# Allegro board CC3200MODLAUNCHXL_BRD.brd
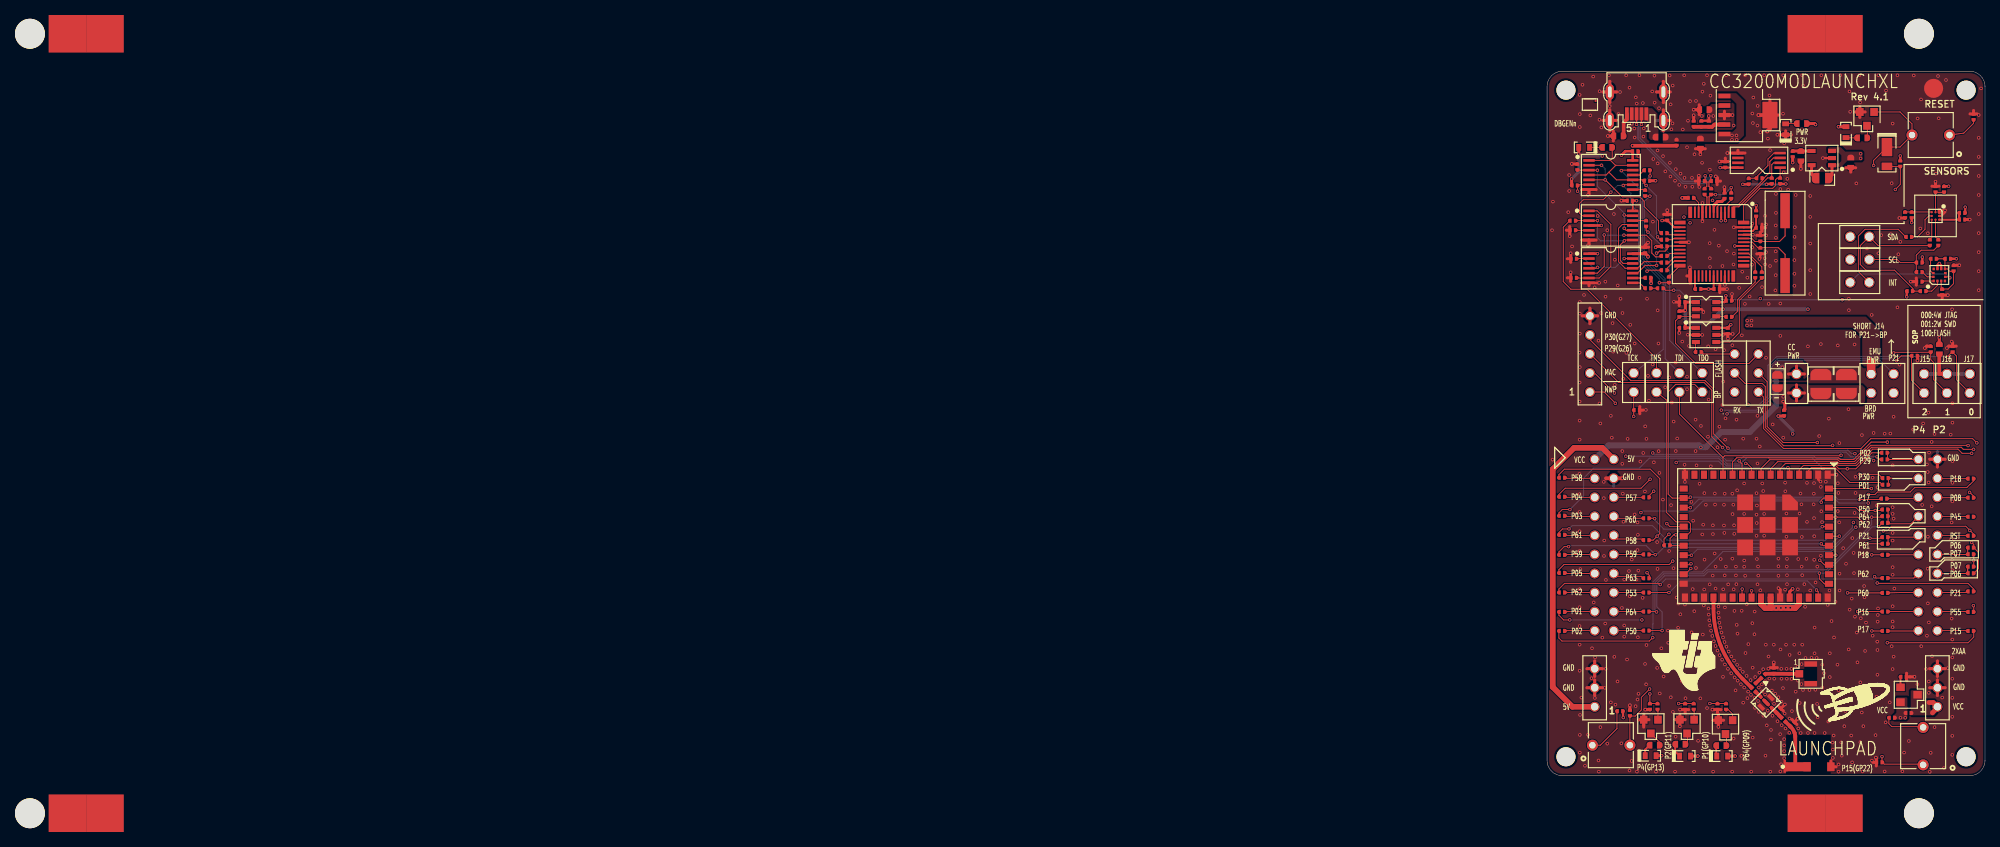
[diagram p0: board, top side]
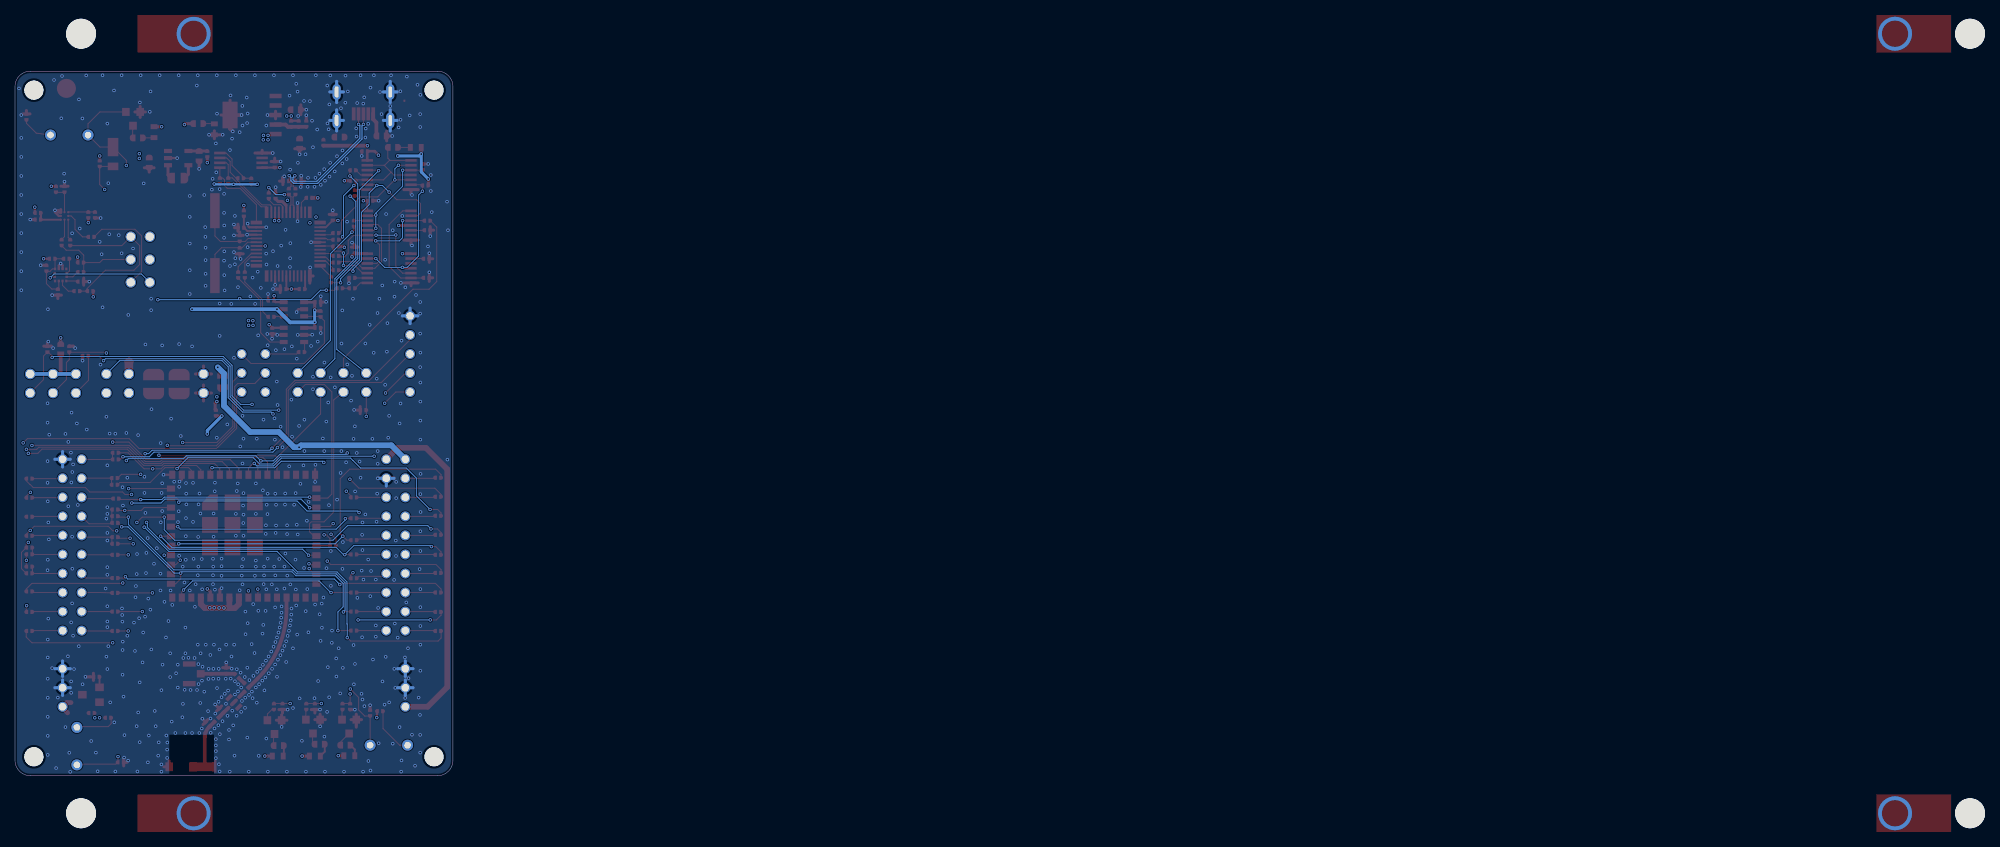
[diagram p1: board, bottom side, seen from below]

Outline 58.42 x 93.98 mm; copper layers: TOP, MID1(L2), MID2(L3), BOTTOM. Coordinates in mm from the lower left corner of the outline.
Outline path: 0,91.95 0,2.03 arc(0.6,0.6) 2.03,0 56.39,0 arc(57.82,0.6) 58.42,2.03 58.42,91.95 arc(57.82,93.38) 56.39,93.98 2.03,93.98 arc(0.6,93.38) 0,91.95

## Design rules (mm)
net group USB_D+: nets USB_D+ USB_DP
net group USB_D-: nets USB_D- USB_DM
net group RF_50OHM_6: nets N17123437 N17123480 N17123972 N17134004 N17134874 N17156940 RF_BG
nets with their own width: min track width 0.127; nets GND

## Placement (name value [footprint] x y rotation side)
C31  15pF  [C-0402S0]  21.59 86.97 180 top
C32  10uF  [C-0603S0]  20.98 88.85 90 top
C33  10uF  [C-0603S0]  20.45 84.33 180 top
C50  0.1uF  [C-0402S0]  54.23 67.69 0 top
C51  0.1uF  [C-0402S0]  55.37 74.19 270 top
C52  0.1uF  [C-0402S0]  52.7 64.52 180 top
C54  33000 pF  [C-0402S0]  23.67 77.37 0 top
C55  0.1uF  [C-0402S0]  28.27 73.1 270 top
C56  0.1uF  [C-0402S0]  16.03 74.47 0 top
C57  0.1uF  [C-0402S0]  22.63 64.92 270 top
C58  0.1uF  [C-0402S0]  23.77 81.53 0 top
C59  30pF  [C-0402S0]  28.45 71.68 0 top
C60  30pF  [C-0402S0]  28.45 70.03 180 top
C63  10uF  [C-0603S0]  33.86 82.65 180 top
C64  1.0pF  [C-0402S0]  32.71 6.87 135 top
C65  100uF  [C-1210]  39.93 52.24 0 top
C66  10uF  [C-0603S0]  40.51 81.79 180 top
C68  0.1uF  [R-0402S0]  18.03 63.18 90 top
C69  0.1uF  [C-0402S0]  24.26 63.37 270 top
C70  0.1uF  [C-0402S0]  18.03 59.75 90 top
C71  100uF  [C-1210]  36.53 52.24 0 top
C72  0.1uF  [C-0402S0]  24.1 59.33 180 top
C73  10pF  [C-0402S0]  28.83 13.28 315 top
C75  0.1uF  [C-0402S0]  11.76 83.31 270 top
C76  0.1uF  [C-0402S0]  13.08 70.1 0 top
C77  0.1uF  [C-0402S0]  11.05 76.71 90 top
D1  LED-Y  [LD-0603A]  39.88 85.85 0 top
D2  LED-G  [LD-0603A]  4.95 83.82 90 top
D4  LED-R  [LD-0603A]  31.83 86.23 0 top
D5  LED-G  [LD-0603A]  13.82 2.66 270 top
D6  LED-Y  [LD-0603A]  18.41 2.61 270 top
D7  LED-R  [LD-0603A]  23.37 2.61 270 top
D9  DIODE  [D-DFLT51AS0]  45.34 82.91 180 top
D13  V5.5MLA  [R-0402S0]  20.62 79.32 90 top
D14  V5.5MLA  [R-0402S0]  22.28 79.32 270 top
E1  AH316M245001-T  [ANT-T77H533_00C]  36.27 1.18 180 top
FB11  60R  [L-0603S0]  15.14 85.19 270 top
FB12  60R  [L-0603S0]  9.53 85.34 90 top
H1  TOOLING HOLE-1PIN-NPTH  [MTH100]  2.52 2.52 0 top
H2  TOOLING HOLE-1PIN-NPTH  [MTH100]  55.9 2.52 0 top
H3  TOOLING HOLE-1PIN-NPTH  [MTH100]  55.9 91.46 0 top
H4  TOOLING HOLE-1PIN-NPTH  [MTH100]  2.52 91.46 0 top
J1  Micro-USB  [CJ-USBSUA-160M3B-L2AT]  11.94 90.17 180 top
J2  jumper  [CN-D2X1-2_54S0]  41.71 71.91 180 top
J3  jumper  [CN-D2X1-2_54S0]  41.71 68.86 180 top
J4  jumper  [CN-D2X1-2_54S0]  41.71 65.81 180 top
J5  DNP  [CN-5X1-2_54]  5.71 56.26 90 top
J6  HEADER_3  [CN-3X1-2_54]  25.02 53.72 90 top
J7  HEADER_3  [CN-3X1-2_54]  28.19 53.72 90 top
J8  jumper  [CN-D2X1-2_54S0]  11.56 52.45 270 top
J9  jumper  [CN-D2X1-2_54S0]  14.61 52.45 270 top
J10  jumper  [CN-D2X1-2_54S0]  17.65 52.45 270 top
J11  jumper  [CN-D2X1-2_54S0]  20.7 52.45 270 top
J12  Jumper  [CN-D2X1-2_54S0]  33.27 52.32 90 top
J13  jumper  [CN-D2X1-2_54S0]  43.23 52.32 90 top
J14  jumper  [CN-D2X1-2_54S0]  46.23 52.32 90 top
J15  jumper  [CN-D2X1-2_54S0]  50.3 52.32 90 top
J16  jumper  [CN-D2X1-2_54S0]  53.35 52.32 90 top
J17  jumper  [CN-D2X1-2_54S0]  56.39 52.32 90 top
J18  CONN_U.FL  [CJ-RF-S3_1X3-3]  35.17 13.59 270 top
J19  HEADER_3  [CN-3X1-2_54]  6.35 11.73 90 top
J20  HEADER_3  [CN-3X1-2_54]  52.07 11.73 90 top
J22  CONN_RCPT_10x2  [CN-10X2-2_54C]  7.62 30.78 270 top
J23  CONN_RCPT_10x2  [CN-10X2-2_54C]  50.8 30.78 270 top
J24  MM8030-2610RJ3  [CN-MM8030S0]  29.21 9.78 225 top
L4  3.6nH  [L-0402S0]  31.53 7.47 225 top
L5  DNP  [L-0402S0]  30.9 8.68 315 top
L6  DNP  [L-0402S0]  30.24 14 0 top
L11  10uH  [L-0805]  36.7 79.73 90 top
NOREF  -  []  49.61 -10.02 90 top
NOREF#2  -  []  54.61 95.98 90 top
NOREF#3  -  []  3.81 90.98 0 top
NOREF#4  -  []  -238.79 103.99 270 top
NOREF#5  -  []  54.61 -2.02 90 top
NOREF#6  -  [unnamed#2]  5.71 89.53 180 top
NOREF#7  -  []  -254.76 115.32 0 top
NOREF#8  -  []  3.81 90.98 180 top
NOREF#9  -  []  6.81 -0.02 90 top
NOREF#10  -  []  -207.39 95.98 0 top
OP1  MD-FIDUCIAL-MARK  [TOP10L-4S0]  -207.39 -0.01 90 top
OP2  MD-FIDUCIAL-MARK  [TOP10R-4S0]  -207.39 93.98 90 top
OP3  MD-FIDUCIAL-MARK  [TOP15L-4S0]  54.61 -0.02 90 top
OP4  MD-FIDUCIAL-MARK  [TOP15R-4S0]  54.61 93.98 90 top
Q7  BSS138LT3G  [SOT-23B]  13.84 6.55 90 top
Q8  BSS138LT3G  [SOT-23B]  18.67 6.55 90 top
Q9  BSS138LT3G  [SOT-23B]  23.8 6.47 90 top
Q10  BSS138LT3G  [SOT-23B]  42.67 87.63 90 top
Q11  AP2323GN  [SOT-23D]  48.29 10.79 180 top
R4  100k  [R-0402S0]  54.1 56.9 0 top
R7  100k  [R-0402S0]  51.18 56.9 0 top
R8  2.7k  [R-0402S0]  49.02 56.01 270 top
R9  270  [R-0603S0]  52.32 56.9 180 top
R10  0 R  [R-0402S0]  1.98 39.75 270 top
R12  0R  [R-0402S0]  16 30.73 90 top
R13  100k  [R-0402S0]  11.96 48.77 270 top
R22  0 R  [R-0402S0]  1.98 29.46 270 top
R28  28  [R-0402S0]  21.89 77.93 180 top
R30  10k  [R-0402S0]  19.18 77.09 270 top
R31  0 R  [R-0402S0]  1.98 24.43 270 top
R32  10k  [R-0402S0]  31.09 79.35 0 top
R34  10k  [R-0402S0]  20.14 64.92 90 top
R35  2.2K  [R-0402S0]  28.32 79.71 270 top
R36  0 R  [R-0402S0]  56.52 24.58 270 top
R55  30.1K  [R-0402S0]  19.56 86.97 180 top
R56  52.3K  [R-0402S0]  20.57 86.97 0 top
R63  DNP  [R-0805]  30.73 52.58 180 top
R64  270  [R-0603S0]  33.99 87 90 top
R69  270  [R-0603S0]  14.35 4.06 270 top
R70  270  [R-0603S0]  17.78 4.19 270 top
R72  DNP  [R-0402S0]  47.75 74.8 0 top
R74  DNP  [R-0402S0]  27.56 12.06 135 top
R75  0 R  [R-0402S0]  27.54 11.46 225 top
R76  DNP  [R-0201S1]  28.71 10.28 45 top
R77  DNP  [R-0201S1]  29.71 9.28 225 top
R86  DNP  [R-0402S0]  52.96 78.23 0 top
R94  270  [R-0603S0]  23.24 4.01 270 top
R95  270  [R-0603S0]  42.04 85.09 270 top
R97  0 R  [R-0402S0]  49.66 67.18 270 top
R98  0 R  [R-0402S0]  53.47 68.96 270 top
R99  0 R  [R-0402S0]  48.64 74.8 180 top
R101  0 R  [R-0402S0]  55.37 75.08 270 top
R102  0 R  [R-0402S0]  49.66 65.91 270 top
R103  0 R  [R-0402S0]  51.56 68.96 90 top
R104  0 R  [R-0402S0]  50.16 64.64 270 top
R106  0 R  [R-0402S0]  51.82 78.23 180 top
R107  0 R  [R-0402S0]  52.2 71.12 0 top
R108  0 R  [R-0402S0]  51.05 71.12 0 top
R109  0 R  [R-0402S0]  17.27 84.45 180 top
R110  0 R  [R-0402S0]  32.77 82.93 0 top
R111  DNP  [R-0402S0]  48.26 71.88 90 top
R112  DNP  [R-0402S0]  31.62 48.39 0 top
R113  0 R  [R-0402S0]  15.11 65.02 90 top
R120  DNP  [R-0402S0]  48.21 8.36 90 top
R168  1k  [R-0402S0]  9.73 8.61 90 top
R169  1k  [R-0402S0]  46 7.72 90 top
R172  3.3K  [R-0402S0]  49.66 68.45 270 top
R173  3.3K  [R-0402S0]  48.39 64.64 90 top
R207  10k  [R-0402S0]  44.32 1.78 90 top
R208  10k  [R-0402S0]  11.05 8.36 0 top
R209  10k  [R-0402S0]  14.73 9.22 180 top
R210  10k  [R-0402S0]  19.56 9.22 180 top
R211  10k  [R-0402S0]  23.88 9.22 180 top
R212  100k  [R-0402S0]  22.73 9.22 0 top
R213  100k  [R-0402S0]  18.41 9.22 0 top
R214  100k  [R-0402S0]  13.72 9.22 0 top
R225  100R  [R-0402S0]  56.9 87.88 180 top
R226  100k  [R-0402S0]  47.12 81.66 180 top
R231  0 R  [R-0402S0]  1.98 32.13 270 top
R237  0 R  [R-0402S0]  1.98 27.05 270 top
R277  0 R  [R-0402S0]  47.55 13.18 90 top
R278  0 R  [R-0402S0]  13.24 26.34 270 top
R279  0 R  [R-0402S0]  13.24 24.43 270 top
R280  0 R  [R-0402S0]  56.52 37.08 270 top
R284  0 R  [R-0402S0]  56.52 21.84 270 top
R285  0 R  [R-0402S0]  45.01 42.19 270 top
R286  0 R  [R-0402S0]  45.14 39.7 270 top
R287  0 R  [R-0402S0]  1.98 37.21 270 top
R288  0 R  [R-0402S0]  1.98 34.67 270 top
R289  0 R  [R-0402S0]  1.98 21.84 270 top
R290  0 R  [R-0402S0]  1.98 19.3 270 top
R291  0 R  [R-0402S0]  13.24 21.89 270 top
R292  0 R  [R-0402S0]  56.52 32 270 top
R293  0 R  [R-0402S0]  56.52 29.54 270 top
R294  0 R  [R-0402S0]  56.52 27 270 top
R295  0 R  [R-0402S0]  56.52 39.62 270 top
R296  DNP  [R-0402S0]  56.52 30.43 270 top
R297  DNP  [R-0402S0]  56.52 27.89 270 top
R298  DNP  [R-0402S0]  45.01 43.08 270 top
R299  DNP  [R-0402S0]  45.14 38.81 270 top
R300  DNP  [R-0402S0]  45.09 26.36 270 top
R301  DNP  [R-0402S0]  45.09 24.38 270 top
R302  10k  [R-0402S0]  26.9 79.3 0 top
R303  33  [R-0402S0]  16.26 66.17 180 top
R304  33  [R-0402S0]  15.62 67.44 90 top
R305  33  [R-0402S0]  15.62 68.45 90 top
R306  33  [R-0402S0]  15.62 69.34 90 top
R307  DNP  [R-0402S0]  45.09 30.93 270 top
R308  DNP  [R-0402S0]  45.09 29.46 270 top
R309  0 R  [R-0402S0]  13.24 37.13 270 top
R310  0 R  [R-0402S0]  45.09 21.89 270 top
R311  0 R  [R-0402S0]  45.09 19.3 270 top
R312  0 R  [R-0402S0]  13.24 34.34 270 top
R313  0 R  [R-0402S0]  56.52 19.3 270 top
R314  10k  [R-0402S0]  15.62 70.61 270 top
R315  10k  [R-0402S0]  13.34 79.38 90 top
R316  33  [R-0402S0]  15.62 72.39 90 top
R317  33  [R-0402S0]  15.62 71.5 90 top
R318  10k  [R-0402S0]  3.68 78.74 270 top
R319  10k  [R-0402S0]  4.04 81.2 0 top
R320  33  [R-0402S0]  13.34 80.77 270 top
R321  33  [R-0402S0]  13.08 77.72 180 top
R322  10k  [R-0402S0]  3.56 66.42 90 top
R323  33  [R-0402S0]  3.43 74.04 90 top
R324  33  [R-0402S0]  13.21 73.66 180 top
R325  10k  [R-0402S0]  13.46 66.42 270 top
R326  270  [R-0603S0]  8 83.82 270 top
R327  33  [R-0402S0]  13.46 65.02 270 top
R328  10k  [R-0402S0]  3.56 68.96 90 top
R329  10k  [R-0402S0]  3.43 72.77 90 top
R330  33  [R-0402S0]  24.26 61.21 270 top
R331  33  [R-0402S0]  20.19 56.52 90 top
R332  33  [R-0402S0]  28.65 66.8 180 top
R333  33  [R-0402S0]  27.76 66.8 180 top
R334  DNP  [R-0402S0]  45.09 34.62 270 top
R335  0 R  [R-0402S0]  13.24 19.35 270 top
R336  DNP  [R-0402S0]  44.96 36.96 270 top
R337  DNP  [R-0402S0]  45.09 31.82 270 top
R338  470  [R-0402S0]  27.89 75.01 0 top
R339  DNP  [R-0402S0]  45.09 35.51 270 top
R340  DNP  [R-0402S0]  13.24 29.51 270 top
R341  0 R  [R-0402S0]  56.52 34.54 270 top
R342  10k  [R-0402S0]  29.97 79.35 0 top
R343  28  [R-0402S0]  21.01 77.93 180 top
R344  DNP  [R-0402S0]  45.09 33.73 270 top
R345  1.5k  [R-0402S0]  24.56 77.37 180 top
R346  DNP  [R-0402S0]  13.24 31.42 270 top
R347  100k  [R-0402S0]  17.65 61.59 0 top
SW1  1BT002-0120L  [SW-D6_2X6_2-2]  51.18 85.47 180 top
SW2  1BT002-0120L  [SW-D6_2X6_2-2]  50.16 3.94 90 top
SW3  1BT002-0120L  [SW-D6_2X6_2-2]  8.55 4.06 180 top
TP1  TP_1206  [ICT100]  51.56 91.69 180 top
U1  TI CC3101 module  [E-PMODULE-S20_5X17_5-54S]  27.91 31.95 180 top
U2  93LC46B-I/MS  [MSOP-8A]  28.27 82.09 0 top
U3  TPS73701  [SOT-223-6]  26.7 88.14 180 top
U4  SN74LVC125APWR  [SSOP-14S0]  8.51 80.14 180 top
U5  FT2232D  [TQFP-48S0]  21.97 70.92 180 top
U6  TMP006  [TBGA-3X3-8C]  51.82 74.68 180 top
U7  SN74LVC126APWR  [SSOP-14S0]  8.51 73.41 180 top
U8  TPS61097-33DBVR  [SOT-23-5]  36.65 82.39 0 top
U9  SN74LVC125APWR  [SSOP-14S0]  8.51 67.69 180 top
U10  BMA222  [TLP-2X2-12]  52.32 66.8 0 top
U11  SN74LVC1T45D  [SOT-23-6]  21.21 58.8 180 top
U12  SN74LVC1T45D  [SOT-23-6]  21.21 62.23 180 top
Y1  6MHz  [O-SMD49S12X4_8S0]  31.75 71.04 180 top

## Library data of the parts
C31 C50-C52 C54-C60 C64 C69 C70 C72 C73 C75-C77 = C-0402S0
C32 C33 C63 C66 = C-0603S0
C65 C71 = C-1210
C68 D13 D14 R4 R7 R8 R10 R12 R13 R22 R30-R32 R34-R36 R55 R56 R72 R74 R75 R86 R97-R99 R101-R104 R106-R113 R120 R168 R169 R172 R173 R207-R214 R225 R226 R231 R237 R277-R280 R284-R325 R327-R342 R344-R347 = R-0402S0
D1 D2 D4-D7 = LD-0603A
D9 = D-DFLT51AS0
E1 = ANT-T77H533_00C
FB11 FB12 = L-0603S0
H1-H4 = MTH100
J1 = CJ-USBSUA-160M3B-L2AT
J2-J4 J8-J17 = CN-D2X1-2_54S0
J5 = CN-5X1-2_54
J6 J7 J19 J20 = CN-3X1-2_54
J18 = CJ-RF-S3_1X3-3
J22 J23 = CN-10X2-2_54C
J24 = CN-MM8030S0
L4-L6 = L-0402S0
L11 = L-0805
OP1 = TOP10L-4S0
OP2 = TOP10R-4S0
OP3 = TOP15L-4S0
OP4 = TOP15R-4S0
Q7-Q10 = SOT-23B
Q11 = SOT-23D
R9 R64 R69 R70 R94 R95 R326 = R-0603S0
R28 R343 = R-0402S0: signal model: R-0402S0_28
R63 = R-0805
R76 R77 = R-0201S1
SW1-SW3 = SW-D6_2X6_2-2
TP1 = ICT100
U1 = E-PMODULE-S20_5X17_5-54S
U2 = MSOP-8A
U3 = SOT-223-6
U4 U7 U9 = SSOP-14S0
U5 = TQFP-48S0
U6 = TBGA-3X3-8C
U8 = SOT-23-5
U10 = TLP-2X2-12
U11 U12 = SOT-23-6
Y1 = O-SMD49S12X4_8S0

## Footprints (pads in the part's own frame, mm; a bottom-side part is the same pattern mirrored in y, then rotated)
ANT-T77H533_00C
  rect 0.406x0.406 smd: 1(3.163,-4.005)
  rect 0.991x1.194 smd: 2(1.595,0) 3(-1.595,0)
C-0402S0
  custom 0.127x0.127 smd: 1(0,-0.406) 2(0,0.406)
C-0603S0
  custom 0.191x0.191 smd: 1(0,-0.686) 2(0,0.686)
C-1210
  custom 0.381x0.381 smd: 1(0,-1.27) 2(0,1.27)
CJ-RF-S3_1X3-3
  rect 0.991x1.041 smd: 1(0,-1.524)
  rect 0.711x1.702 smd: 2(1.311,0) 3(-1.311,0)
CJ-USBSUA-160M3B-L2AT
  rect 0.508x1.753 smd: 1(-1.3,1.877) 2(-0.65,1.877) 3(0,1.877) 4(0.65,1.877) 5(1.3,1.877)
  oval 1.092x2.083 hole 0.483x1.473: S1(3.575,-1.05) S2(-3.575,-1.05) S3(3.575,2.75) S4(-3.575,2.75)
CN-3X1-2_54
  round 1.321 hole 0.991: 1(-2.54,0) 2(0,0) 3(2.54,0)
CN-5X1-2_54
  round 1.321 hole 0.991: 1(-5.08,0) 2(-2.54,0) 3(0,0) 4(2.54,0) 5(5.08,0)
CN-10X2-2_54C
  round 1.321 hole 0.991: 1(-11.43,-1.27) 2(-11.43,1.27) 3(-8.89,-1.27) 4(-8.89,1.27) 5(-6.35,-1.27) 6(-6.35,1.27) 7(-3.81,-1.27) 8(-3.81,1.27) 9(-1.27,-1.27) 10(-1.27,1.27) 11(1.27,-1.27) 12(1.27,1.27) 13(3.81,-1.27) 14(3.81,1.27) 15(6.35,-1.27) 16(6.35,1.27) 17(8.89,-1.27) 18(8.89,1.27) 19(11.43,-1.27) 20(11.43,1.27)
CN-D2X1-2_54S0
  round 1.397 hole 1.092: 1(-1.27,0) 2(1.27,0)
CN-MM8030S0
  rect 0.356x0.356 smd: 1(0,-0.978) 4(0,0.978)
  rect 0.508x1.016 smd: 2(-0.904,0) 3(0.904,0)
D-DFLT51AS0
  rect 1.422x1.016 smd: 1(0,1.626)
  rect 1.422x2.438 smd: 2(0,-0.95)
E-PMODULE-S20_5X17_5-54S
  rect 0.813x1.092 smd: 1(-9.525,-8.196) 2(-8.255,-8.196) 3(-6.985,-8.196) 4(-5.715,-8.196) 5(-4.445,-8.196) 6(-3.175,-8.196) 7(-1.905,-8.196) 8(-0.635,-8.196) 9(0.635,-8.196) 10(1.905,-8.196) 11(3.175,-8.196) 12(4.445,-8.196) 13(5.715,-8.196) 14(6.985,-8.196) 15(8.255,-8.196) 16(9.525,-8.196) 28(9.525,8.196) 29(8.255,8.196) 30(6.985,8.196) 31(5.715,8.196) 32(4.445,8.196) 33(3.175,8.196) 34(1.905,8.196) 35(0.635,8.196) 36(-0.635,8.196) 37(-1.905,8.196) 38(-3.175,8.196) 39(-4.445,8.196) 40(-5.715,8.196) 41(-6.985,8.196) 42(-8.255,8.196) 43(-9.525,8.196)
  rect 1.092x0.813 smd: 17(9.696,-6.35) 18(9.696,-5.08) 19(9.696,-3.81) 20(9.696,-2.54) 21(9.696,-1.27) 22(9.696,0) 23(9.696,1.27) 24(9.696,2.54) 25(9.696,3.81) 26(9.696,5.08) 27(9.696,6.35) 44(-9.696,6.35) 45(-9.696,5.08) 46(-9.696,3.81) 47(-9.696,2.54) 48(-9.696,1.27) 49(-9.696,0) 50(-9.696,-1.27) 51(-9.696,-2.54) 52(-9.696,-3.81) 53(-9.696,-5.08) 54(-9.696,-6.35)
  custom 0.527x0.527 smd: 55(-4.5,-4.5)
  rect 2.108x2.108 smd: 56(-1.5,-4.5) 57(1.5,-4.5) 58(-4.5,-1.5) 59(-1.5,-1.5) 60(1.5,-1.5) 61(-4.5,1.5) 62(-1.5,1.5) 63(1.5,1.5)
ICT100
  round 2.54 smd: 1(0,0)
L-0402S0
  custom 0.127x0.127 smd: 1(0,-0.406) 2(0,0.406)
L-0603S0
  custom 0.191x0.191 smd: 1(0,-0.686) 2(0,0.686)
L-0805
  custom 0.254x0.254 smd: 1(0,-0.889) 2(0,0.889)
LD-0603A
  rect 0.914x0.66 smd: 1(0,0.728) 2(0,-0.728)
MSOP-8A
  rect 1.524x0.356 smd: 1(2.819,-0.975) 2(2.819,-0.325) 3(2.819,0.325) 4(2.819,0.975) 5(-2.819,0.975) 6(-2.819,0.325) 7(-2.819,-0.325) 8(-2.819,-0.975)
MTH100
  round 2.54 hole 2.54 unplated: (0,0)
O-SMD49S12X4_8S0
  rect 1.27x4.674 smd: 1(0,-4.331) 2(0,4.331)
R-0201S1
  custom 0.076x0.076 smd: 1(0,-0.229) 2(0,0.229)
R-0402S0
  custom 0.127x0.127 smd: 1(0,-0.406) 2(0,0.406)
R-0603S0
  custom 0.191x0.191 smd: 1(0,-0.686) 2(0,0.686)
R-0805
  custom 0.254x0.254 smd: 1(0,-0.889) 2(0,0.889)
SOT-23-5
  rect 1.067x0.559 smd: 1(1.359,-0.95) 2(1.359,0) 3(1.359,0.95) 4(-1.359,0.95) 5(-1.359,-0.95)
SOT-23-6
  rect 1.067x0.559 smd: 1(1.359,-0.95) 2(1.359,0) 3(1.359,0.95) 4(-1.359,0.95) 5(-1.359,0) 6(-1.359,-0.95)
SOT-23B
  rect 1.067x1.016 smd: 1(0.92,-0.951) 2(0.92,0.951) 3(-0.921,0)
SOT-23D
  rect 1.143x1.016 smd: 1(1.143,-0.991) 2(1.143,0.991) 3(-1.143,0)
SOT-223-6
  rect 1.6x0.61 smd: 1(3.035,-2.54) 2(3.035,-1.27) 3(3.035,0) 4(3.035,1.27) 5(3.035,2.54)
  rect 2.007x3.556 smd: 6(-3.035,0)
SSOP-14S0
  rect 1.524x0.356 smd: 1(2.918,-1.95) 2(2.918,-1.3) 3(2.918,-0.65) 4(2.918,0) 5(2.918,0.65) 6(2.918,1.3) 7(2.918,1.95) 8(-2.918,1.95) 9(-2.918,1.3) 10(-2.918,0.65) 11(-2.918,0) 12(-2.918,-0.65) 13(-2.918,-1.3) 14(-2.918,-1.95)
SW-D6_2X6_2-2
  round 1.473 hole 0.864: T1(-2.5,0) T2(2.5,0)
TBGA-3X3-8C
  round 0.305 smd: A1(-0.5,-0.5) A2(-0.5,0) A3(-0.5,0.5) B1(0,-0.5) B3(0,0.5) C1(0.5,-0.5) C2(0.5,0) C3(0.5,0.5)
TLP-2X2-12
  rect 0.305x0.356 smd: 1(-0.75,-0.803) 2(-0.25,-0.803) 3(0.25,-0.803) 4(0.75,-0.803) 7(0.75,0.803) 8(0.25,0.803) 9(-0.25,0.803) 10(-0.75,0.803)
  rect 0.356x0.305 smd: 5(0.803,-0.25) 6(0.803,0.25) 11(-0.803,0.25) 12(-0.803,-0.25)
TOP10L-4S0
  round 3.988 hole 3.988 unplated: (-5.004,-5.004)
  rect 5.004x5.004 smd: (-5.004,-10.008) (-5.004,-15.011)
  round 1.016 smd: (-5.004,-15.011) 1(-5.004,-10.008)
TOP10R-4S0
  round 3.988 hole 3.988 unplated: (5.004,-5.004)
  rect 5.004x5.004 smd: (5.004,-10.008) (5.004,-15.011)
  round 1.016 smd: (5.004,-15.011) 1(5.004,-10.008)
TOP15L-4S0
  round 1.016 smd: (-5.001,20.018) 1(-5.001,15.014)
  rect 5.004x5.004 smd: (-5.001,20.018) (-5.001,15.014)
  round 3.988 hole 3.988 unplated: (-5.001,5.006)
TOP15R-4S0
  round 1.016 smd: (5.006,20.018) 1(5.006,15.014)
  rect 5.004x5.004 smd: (5.006,20.018) (5.006,15.014)
  round 3.988 hole 3.988 unplated: (5.006,5.006)
TQFP-48S0
  rect 0.508x1.524 smd: 1(-2.878,-4.249) 12(2.878,-4.249) 25(2.878,4.249) 36(-2.878,4.249)
  rect 0.254x1.524 smd: 2(-2.251,-4.249) 3(-1.751,-4.249) 4(-1.25,-4.249) 5(-0.75,-4.249) 6(-0.25,-4.249) 7(0.25,-4.249) 8(0.75,-4.249) 9(1.25,-4.249) 10(1.75,-4.249) 11(2.25,-4.249) 26(2.25,4.249) 27(1.75,4.249) 28(1.25,4.249) 29(0.75,4.249) 30(0.25,4.249) 31(-0.25,4.249) 32(-0.75,4.249) 33(-1.25,4.249) 34(-1.751,4.249) 35(-2.251,4.249)
  rect 1.524x0.508 smd: 13(4.249,-2.878) 24(4.249,2.878) 37(-4.249,2.878) 48(-4.249,-2.878)
  rect 1.524x0.254 smd: 14(4.249,-2.251) 15(4.249,-1.751) 16(4.249,-1.25) 17(4.249,-0.75) 18(4.249,-0.25) 19(4.249,0.25) 20(4.249,0.75) 21(4.249,1.25) 22(4.249,1.75) 23(4.249,2.25) 38(-4.249,2.25) 39(-4.249,1.75) 40(-4.249,1.25) 41(-4.249,0.75) 42(-4.249,0.25) 43(-4.249,-0.25) 44(-4.249,-0.75) 45(-4.249,-1.25) 46(-4.249,-1.751) 47(-4.249,-2.251)
unnamed#2
  rect 0.254x0.305 smd: 1(-0.762,-0.508)

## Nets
GND: C32.2 C33.2 C50.2 C51.2 C52.2 C54.2 C55.2 C56.2 C57.2 C58.2 C59.2 C60.2 C63.2 C64.1 C65.2 C66.2 C68.2 C69.2 C70.2 C71.2 C72.2 C75.2 C76.2 C77.2 D4.2 D13.2 D14.2 E1.2 E1.3 FB12.2 J1.S1 J1.S2 J1.S3 J1.S4 J5.5 J18.2 J18.3 J19.2 J19.3 J20.2 J20.3 J22.4 J23.2 J24.2 J24.3 L5.2 L6.2 Q7.2 Q8.2 Q9.2 Q10.2 R4.2 R7.2 R8.2 R13.2 R55.1 R72.1 R102.1 R106.1 R207.2 R208.2 R212.1 R213.1 R214.1 R225.1 R277.1 R319.2 R322.2 R325.2 R328.2 R329.2 TP1.1 U1.1 U1.2 U1.16 U1.27 U1.28 U1.30 U1.32 U1.38 U1.43 U1.55 U1.56 U1.57 U1.58 U1.59 U1.60 U1.61 U1.62 U1.63 U2.5 U3.3 U3.6 U4.7 U5.9 U5.18 U5.25 U5.34 U5.45 U5.47 U6.A1 U6.A2 U7.7 U8.2 U9.7 U10.8 U10.9 U11.2 U11.5 U12.2
VBAT_CC: C65.1 C71.1 J12.1 R63.2 R112.2 U1.36 U1.37 U1.40
VBUS_USB1: C33.1 FB11.2 R109.1 R338.2 U3.1 U3.5 U5.3 U5.4 U5.42
VCC_BRD: C66.1 C68.1 C70.1 D1.1 D5.1 D6.1 D7.1 J12.2 J13.1 J22.1 L11.1 Q11.2 R9.1 R63.1 R64.1 R86.2 R98.2 R99.2 R101.2 R120.2 R168.1 R169.1 R172.2 R173.2 R226.1 R347.2 U8.1 U8.3 U11.1 U12.1 U12.5
VCC_DCDC_3V3: C63.1 R110.2 U8.4
VCC_LDO_3V3: C31.1 C32.1 C56.1 C57.1 C58.1 C69.1 C72.1 C75.1 C76.1 C77.1 D2.1 J13.2 R30.1 R32.1 R34.1 R56.2 R302.1 R314.1 R315.1 R318.1 R342.1 U2.8 U3.2 U4.14 U5.14 U5.31 U7.4 U7.14 U9.1 U9.14 U11.6 U12.6
VCC_MCU_5V: J19.1 J22.2 R109.2
VDD_FLASH: R110.1 R112.1 U1.39
BRD_JTAG_TCK: J8.1 R320.2
BRD_JTAG_TDI: J10.1 R321.2
BRD_JTAG_TDO: J11.1 R324.2
BRD_JTAG_TMS: J9.1 R323.2
CC_GPIO_00: R335.2 R344.1 U1.44
CC_GPIO_01: J7.2 U1.46
CC_GPIO_02: J6.2 U1.47
CC_GPIO_03: R10.1 R346.2 U1.48
CC_GPIO_04: R22.1 R340.2 U1.49
CC_GPIO_05: J5.2 R301.1 R312.2 U1.50
CC_GPIO_06: R231.1 R307.1 U1.51
CC_GPIO_07: J5.1 R31.1 R300.1 R339.1 U1.52
CC_GPIO_08: R278.2 U1.53
CC_GPIO_09: R211.1 R212.2 R291.2 R334.1 U1.54
CC_GPIO_10: J3.2 R210.1 R213.2 R289.1 R299.1 U1.3
CC_GPIO_11: J2.2 R209.1 R214.2 R290.1 R298.1 U1.4
CC_GPIO_12: R288.1 U1.9
CC_GPIO_13: J4.1 R111.2 R208.1 R287.1 SW3.T1 U1.10
CC_GPIO_14: R237.1 U1.5
CC_GPIO_15: R294.2 R296.2 U1.6
CC_GPIO_16: R293.2 R297.2 U1.7
CC_GPIO_17: R280.2 U1.8
CC_GPIO_22: R207.1 R313.2 SW2.T1 U1.11
CC_GPIO_23: J10.2 R310.1 U1.12
CC_GPIO_24: J11.2 R311.1 R336.1 U1.18
CC_GPIO_26: J5.3 R285.1 U1.25
CC_GPIO_27: J5.4 R286.1 U1.26
CC_GPIO_28: R295.2 R308.1 U1.19
CC_GPIO_30: R279.2 U1.42
CC_GPIO_31: R341.2
CC_NRESET: D9.2 Q10.1 R113.1 SW1.T2 U1.35
DBG_RST_N: R314.2 U5.19 U9.10
DBGENN: R315.2 R317.2 R326.2 U4.1 U4.4 U4.10 U4.13
DBGMOD: R316.2 U4.2 U4.5
FT_CS: R306.2 U7.9 U9.5
FT_DI: R305.2 U7.11 U9.11
FT_DO: R304.2 U4.9 U7.2
FT_SK: R303.2 U4.12
FTDI_RX: R330.2 R333.2
FTDI_TX: R332.2 U11.4
JTAG_TCK: J8.2 R13.1 U1.21
JTAG_TMS: J9.2 U1.22
LP_GPIO_01: J7.1 R284.2
LP_GPIO_02: J6.1 R309.2
LP_GPIO_25: J14.1 R36.2 R337.1
LP_RESET_OUT: D9.1 R226.2 R292.2
RF_BG: R74.2 R75.1 U1.31
SENS_I2C_SCL: J3.1 R97.1 R107.1 R172.1
SENS_I2C_SDA: J2.1 R104.1 R108.1 R173.1
SOP0: J17.1 R4.1 U1.34
SOP1: J16.1 R7.1 U1.24
SOP2/TCXO_EN: J15.1 R8.1 R12.2
SRSTN: R113.2 R327.2
TEMP_INTR: R111.1 U6.C2
USB_D+: D14.1 J1.3 R28.1
USB_D-: D13.1 J1.2 R343.1
USB_DM: R343.2 U5.8
USB_DP: R28.2 R345.1 U5.7
N185612: C50.1 C52.1 R98.1 R103.1 U10.3 U10.7
N185801: C51.1 R101.1 U6.A3
N186121: R102.2 U10.1
N186159: R103.2 U10.11
N186206: R97.2 U10.12
N186210: R104.2 U10.2
N187169: R72.2 R99.1 U6.C1
N187173: R86.1 R106.2 U6.B1
N187525: R107.2 U6.B3
N187543: R108.2 U6.C3
N187626: J4.2 U10.5
N195183: D4.1 R64.2
N195451: C31.2 R55.2 R56.1 U3.4
N292143: J20.1 Q11.3 R120.1
N311613: R225.2 SW1.T1
N311877: R168.2 SW3.T2
N311889: R169.2 SW2.T2
N312530: D7.2 R94.1
N312602: D5.2 R69.1
N312606: D6.2 R70.1
N312650: Q9.3 R94.2
N312654: Q8.3 R70.2
N312670: Q7.3 R69.2
N312782: Q7.1 R209.2
N312798: Q8.1 R210.2
N312802: Q9.1 R211.2
N329065: Q11.1 R277.2
N394921: L11.2 U8.5
N487570: C54.1 U5.6
N487672: C55.1 R338.1 U5.46
N487804: R345.2 U5.5
N487824: R34.2 U5.26
N487832: R30.2 U5.10
N487932: R333.1 U5.39
N488104: R332.1 U5.40
N488180: R342.2 U2.2 U5.1
N488188: R32.2 U2.1 U5.48
N488454: R303.1 U5.24
N488458: R304.1 U5.23
N488478: R35.1 R302.2 U2.4
N488614: R35.2 U2.3 U5.2
N488778: C60.1 U5.43 Y1.2
N488782: C59.1 U5.44 Y1.1
N489641: R305.1 U5.22
N489651: R306.1 U5.21
N490588: FB11.1 J1.1
N490596: FB12.1 J1.5
N507782: R317.1 U5.17
N507786: R316.1 U5.16
N508362: R318.2 U4.6 U9.4 U9.13
N508615: R319.1 U4.3 U7.10 U7.13
N509670: R320.1 U4.11
N509674: R321.1 U4.8
N511498: R322.1 U7.1 U9.6
N512182: R323.1 U7.3 U7.8 U9.12
N512199: R324.1 U7.12
N517852: R325.1 U9.9
N517913: D2.2 R326.1
N518669: R327.1 U9.8
N519131: R329.1 U7.5
N519138: R328.1 U9.2
N16837579: J15.2 J16.2 J17.2 R9.2
N16966302: J14.2 R12.1 U1.23
N17067937: J22.18 R291.1
N17067943: J22.9 R231.2
N17067945: J22.13 R237.2
N17067955: J22.14 R278.1
N17067957: J22.16 R279.1
N17067979: J23.6 R280.1
N17067993: J23.18 R284.1
N17068333: J23.8 R341.1
N17068401: J7.3 R347.1 U12.3
N17068413: J22.10 R346.1
N17068423: J22.12 R340.1
N17068425: R330.1 U12.4
N17068635: J22.3 R10.2
N17068637: J22.19 R290.2
N17068639: J22.5 R287.2
N17068641: J22.7 R288.2
N17068645: J22.15 R31.2
N17068647: J22.17 R289.2
N17068649: J6.3 R331.1
N17068681: R331.2 U11.3
N17068737: J23.7 R334.2 R339.2 R344.2
N17068769: J23.16 R36.1
N17068771: J23.14 R294.1 R297.1
N17068783: J23.4 R295.1
N17068785: J23.10 R292.1
N17068787: J23.12 R293.1 R296.1
N17068892: J23.3 R286.2 R299.2
N17068894: J23.5 R336.2
N17068898: J23.9 R307.2 R337.2
N17068900: J23.11 R308.2
N17068902: J23.13 R300.2
N17068904: J23.15 R301.2
N17068906: J23.17 R310.2
N17068908: J23.19 R311.2
N17068924: J23.1 R285.2 R298.2
N17069150: J22.6 R309.1
N17069152: J22.8 R312.1
N17069176: J22.11 R22.2
N17069198: J23.20 R313.1
N17069292: J22.20 R335.1
N17097905: D1.2 R95.1
N17097907: Q10.3 R95.2
N17123437: C73.2 J18.1 L6.1
N17123480: C73.1 R74.1
N17123972: J24.4 L4.1 L5.1 R77.2
N17134004: C64.2 E1.1 L4.2
N17134874: J24.1 R75.2 R76.2
N17156940: R76.1 R77.1

Pads without a net: J1 4; NOREF#6 1; OP1 1; OP2 1; OP3 1; OP4 1; U1 13 14 15 17 20 29 33 41 45; U2 6 7; U5 11 12 13 15 20 27 28 29 30 32 33 35 36 37 38 41; U7 6; U9 3; U10 4 6 10

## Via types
v1: diameter 0.457, hole 0.254, TOP to BOTTOM, 1048 vias

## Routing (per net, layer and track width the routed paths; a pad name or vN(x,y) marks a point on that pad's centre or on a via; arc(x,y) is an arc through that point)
GND: length 305.8
  TOP w0.305: v1(24,64.92) 23.98,64.9 23.06,64.9 C57.2 ; v1(28.32,68.94) 28.45,69.06 C60.2 ; C70.2 v1(17.63,59.05) ; 18.39,40.89 U1.16 v1(18.39,39.19) ; v1(24.91,73.17) U5.47 27.17,73.17 27.3,73.3 ; v1(20.73,73.96) 20.72,73.97 U5.9 20.72,76.4 v1(20.73,76.4) ; v1(20.7,58.8) U11.2 18.8,58.8 v1(18.77,58.83) ; U8.2 v1(36.79,82.39) ; v1(12.17,82.68) C75.2 ; C59.2 v1(29.21,72.09) ; U12.2 20.6,62.23 20.85,61.98 v1(20.85,61.85) ; v1(36.47,39.24) 36.44,39.24 36.17,39.52 U1.2 ; U6.A2 52.58,74.68 53.09,75.18 v1(53.09,75.44) 52.58,75.44 U6.A1 ; U5.45 v1(27.46,72.17) ; v1(38.61,40.15) U1.1 ; v1(19.05,67.82) 19.05,66.71 U5.25 ; C72.2 v1(24.77,58.93) ; U11.5 v1(23.44,58.8) ; U5.34 23.72,65.74 23.72,65.74 v1(23.72,65.48) ; C69.2 v1(24.66,64.26) ; U10.8 52.57,68.08 v1(52.32,68.33) 52.07,68.08 U10.9 ; C68.2 v1(17.63,63.96)
  TOP w0.356: R322.2 v1(3.15,67.16) ; U9.7 v1(6.94,65.74)
  TOP w0.406: R212.1 v1(22.05,8.81) ; R212.1 23.2,8.81 ; R212.1 22.73,8.36 ; C57.2 23.04,65.39 ; C57.2 v1(24,64.92) ; C57.2 23.04,64.45 ; C58.2 v1(22.99,81.94) ; C58.2 24.25,81.94 ; C58.2 23.77,82.39 ; C56.2 16.5,74.88 ; C56.2 v1(16.03,75.44) ; C56.2 15.56,74.88 ; U2.5 25.45,83.44 ; U2.5 26.4,83.07 ; U2.5 v1(24.04,83.07) ; 5.32,11.73 J19.2 ; J19.2 6.35,12.76 ; J19.2 7.38,11.73 ; J19.2 6.35,10.7 ; 52.07,13.24 J20.3 ; J20.3 53.1,14.27 ; J20.3 52.07,15.3 ; J20.3 51.04,14.27 ; C63.2 v1(33.86,80.95) ; C64.1 v1(33.43,7.59) ; C64.1 33.33,6.83 ; C64.1 32.66,7.49 ; R277.1 47.96,13.65 ; R277.1 47.96,12.71 ; R277.1 v1(49.02,13.18) ; R208.2 v1(11.05,9.4) ; 28.45,72.53 C59.2 27.98,72.09 ; C33.2 21.1,83.64 ; C33.2 19.8,83.64 ; C33.2 v1(20.45,82.91) ; C54.2 23.67,78.49 v1(23.65,78.51) ; 24.1,58.48 C72.2 23.63,58.93 ; J1.S2 15.51,92.63 ; J1.S2 14.6,91.22 ; J1.S2 16.43,91.22 ; J1.S2 15.51,89.81 ; v1(5.46,77.47) 5.59,77.6 U4.7 ; C51.2 v1(56.39,74.19) ; U3.3 v1(24.74,88.14) ; U3.3 23.66,87.64 ; U3.3 23.66,88.63 ; J20.2 52.07,12.76 ; J20.2 51.04,11.73 ; J20.2 53.1,11.73 ; J20.2 52.07,10.7 ; R207.2 43.92,2.36 v1(43.87,2.41) ; R207.2 43.47,1.78 ; R207.2 43.92,1.31 ; 8.36,86.01 J1.S3 ; J1.S3 8.36,88.83 ; J1.S3 7.45,87.42 ; J1.S3 9.28,87.42 ; Q9.2 v1(22.85,6.51) ; Q9.2 22.85,8.12 ; Q9.2 22.15,7.39 ; Q9.2 23.55,7.39 ; R4.2 54.57,57.3 ; R4.2 54.1,57.75 ; R4.2 53.59,57.3 v1(53.34,57.05) ; 52.66,75.18 U6.A1 52.32,75.52 ; 2.7,66.42 R322.2 3.15,65.95 ; C32.2 20.29,89.5 ; C32.2 20.29,88.2 ; C32.2 v1(19.56,88.85) ; D14.2 22.71,79.35 22.71,79.76 v1(22.5,79.96) ; D14.2 23.13,79.32 ; D14.2 22.68,79.8 ; D14.2 22.68,78.85 ; J5.5 5.71,62.37 ; J5.5 6.74,61.34 ; J5.5 5.71,60.31 ; J5.5 4.69,61.34 ; J19.3 6.35,15.3 ; J19.3 7.38,14.27 ; J19.3 5.32,14.27 ; J19.3 6.35,13.24 ; R13.2 12.82,48.77 ; R13.2 12.37,49.24 ; R13.2 12.37,48.3 ; v1(30.86,25.02) 31.09,24.79 U1.38 ; 17.63,62.71 C68.2 17.18,63.18 ; R329.2 v1(3.02,71.98) ; R329.2 3.02,73.24 ; R329.2 2.58,72.77 ; 31.83,84.98 D4.2 ; D4.2 31.83,86.03 ; D4.2 v1(30.72,85.5) ; D4.2 v1(32.54,85.5) ; 51.34,78.64 R106.1 ; R106.1 52.29,78.64 ; R106.1 v1(51.82,79.25) ; 18.65,66.67 U5.25 ; U5.25 19.09,67.62 ; U5.25 19.09,65.71 ; Q7.2 13.59,7.47 ; Q7.2 12.89,6.48 ; Q7.2 12.19,7.47 ; Q7.2 12.89,8.2 ; 3.15,68.49 R328.2 ; R328.2 v1(3.15,69.7) ; R328.2 2.7,68.96 ; 19.77,79.32 D13.2 ; D13.2 20.24,79.35 v1(20.24,80.04) ; D13.2 20.22,78.85 ; D13.2 20.22,79.8 ; C50.2 v1(54.99,68.1) ; 29.77,14.41 L6.2 ; L6.2 v1(30.24,15.11) ; L6.2 30.71,14.41 ; R213.1 18.89,8.81 ; R213.1 18.41,8.36 ; R213.1 v1(17.73,8.81) ; FB12.2 v1(8.1,85.34) ; FB12.2 8.84,84.7 ; FB12.2 8.84,85.99 ; L5.2 31.52,8.63 ; L5.2 v1(31.72,9.5) ; L5.2 30.85,9.3 ; U4.7 6.54,78.19 ; U4.7 4.64,78.19 ; v1(50.39,57.05) 50.65,57.3 R7.2 ; Q8.2 17.72,8.2 ; Q8.2 18.42,7.47 ; Q8.2 v1(17.72,6.58) ; Q8.2 17.02,7.47 ; U7.7 5.59,70.87 v1(5.46,70.74) ; U7.7 6.54,71.46 ; U7.7 4.64,71.46 ; 15.51,86.01 J1.S4 ; J1.S4 16.43,87.42 ; J1.S4 15.51,88.83 ; Q10.2 41.72,89.27 ; Q10.2 41.02,88.55 ; Q10.2 42.42,88.55 ; Q10.2 41.72,87.83 ; 52.7,63.66 C52.2 ; C52.2 v1(53.47,64.11) ; C52.2 52.23,64.11 ; R102.1 49.25,66.38 ; R102.1 49.25,65.44 ; R102.1 v1(48.51,65.91) ; v1(3.3,81.61) 3.31,81.61 R319.2 ; R225.1 57.37,88.29 ; R225.1 56.9,88.74 ; R225.1 56.42,88.29 ; v1(49.4,55.37) 49.43,55.4 R8.2 ; 37.86,1.97 E1.3 38.55,1.18 ; 39.86,81.1 C66.2 ; C66.2 40.51,80.53 ; C66.2 41.16,81.1 ; R55.1 v1(19.56,88.11) ; J1.S1 8.36,92.63 ; J1.S1 7.45,91.22 ; J1.S1 8.36,89.81 ; J1.S1 9.28,91.22 ; C77.2 v1(9.91,76.71) ; 27.98,69.62 C60.2 28.92,69.62 ; 52.07,41.18 J23.2 ; J23.2 51.04,42.21 ; J23.2 53.1,42.21 ; 12.61,70.51 C76.2 ; C76.2 13.55,70.51 ; C76.2 13.08,70.74 v1(13.46,71.12) ; 4.64,65.74 U9.7 5.59,65.37 ; 30.93,88.14 U3.6 29.73,90.11 ; 28.68,72.63 C55.2 ; C55.2 29.12,73.1 ; C55.2 28.68,73.57 ; R325.2 v1(13.87,65.68) ; R214.1 v1(13.08,8.81) ; R72.1 v1(46.99,74.4) ; U5.18 v1(18.92,71.17)
  TOP w0.508: 7.86,39.67 J22.4 v1(10.03,39.67) ; v1(29.36,85.95) 29.73,86.32 U3.6 v1(28.19,88.14)
  MID1(L2) w0.406: J5.5 6.69,61.34 ; J5.5 4.74,61.34 ; J5.5 5.71,62.32 ; J5.5 5.71,60.36 ; J20.2 53.05,11.73 ; J20.2 51.09,11.73 ; J20.2 52.07,10.75 ; J20.2 52.07,12.71 ; 5.37,11.73 J19.2 ; J19.2 7.33,11.73 ; J19.2 6.35,10.75 ; J19.2 6.35,12.71 ; J1.S3 9.11,87.42 ; J1.S3 8.36,88.65 ; J1.S3 8.36,86.19 ; J1.S3 7.61,87.42 ; J1.S2 15.51,92.45 ; J1.S2 14.76,91.22 ; J1.S2 15.51,89.99 ; J1.S2 16.26,91.22 ; J22.4 9.87,39.67 ; J22.4 7.91,39.67 ; J22.4 8.89,40.65 ; J22.4 8.89,38.69 ; J1.S1 8.36,92.45 ; J1.S1 8.36,89.99 ; J1.S1 7.61,91.22 ; J1.S1 9.11,91.22 ; 6.35,13.29 J19.3 ; J19.3 5.37,14.27 ; J19.3 6.35,15.25 ; J19.3 7.33,14.27 ; J20.3 52.07,15.25 ; J20.3 53.05,14.27 ; J20.3 52.07,13.29 ; J20.3 51.09,14.27 ; 15.51,86.19 J1.S4 ; J1.S4 15.51,88.65 ; J1.S4 14.76,87.42 ; J1.S4 16.26,87.42 ; 52.07,41.23 J23.2 ; J23.2 52.07,43.19 ; J23.2 53.05,42.21 ; J23.2 51.09,42.21
  MID2(L3) w0.406: 15.51,89.99 J1.S2 ; J1.S2 14.76,91.22 ; J1.S2 16.26,91.22 ; J1.S2 15.51,92.45 ; 5.37,11.73 J19.2 ; J19.2 6.35,12.71 ; J19.2 6.35,10.75 ; J19.2 7.33,11.73 ; J20.3 52.07,15.25 ; J20.3 53.05,14.27 ; J20.3 52.07,13.29 ; J20.3 51.09,14.27 ; J20.2 53.05,11.73 ; J20.2 51.09,11.73 ; J20.2 52.07,10.75 ; J20.2 52.07,12.71 ; 8.89,38.69 J22.4 ; J22.4 9.87,39.67 ; J22.4 7.91,39.67 ; J22.4 8.89,40.65 ; 6.35,13.29 J19.3 ; J19.3 7.33,14.27 ; J19.3 6.35,15.25 ; J19.3 5.37,14.27 ; J1.S4 15.51,88.65 ; J1.S4 15.51,86.19 ; J1.S4 14.76,87.42 ; J1.S4 16.26,87.42 ; J1.S1 8.36,92.45 ; J1.S1 7.61,91.22 ; J1.S1 9.11,91.22 ; J1.S1 8.36,89.99 ; 5.71,60.36 J5.5 ; J5.5 4.74,61.34 ; J5.5 5.71,62.32 ; J5.5 6.69,61.34 ; 7.61,87.42 J1.S3 ; J1.S3 8.36,88.65 ; J1.S3 9.11,87.42 ; J1.S3 8.36,86.19 ; 52.07,41.23 J23.2 ; J23.2 51.09,42.21 ; J23.2 53.05,42.21 ; J23.2 52.07,43.19
  BOTTOM w0.406: J1.S3 9.28,87.42 ; J1.S3 8.36,86.01 ; J1.S3 8.36,88.83 ; J1.S3 7.45,87.42 ; J20.2 52.07,12.76 ; J20.2 53.1,11.73 ; J20.2 52.07,10.7 ; J20.2 51.04,11.73 ; 52.07,13.24 J20.3 ; J20.3 52.07,15.3 ; J20.3 53.1,14.27 ; J20.3 51.04,14.27 ; 15.51,86.01 J1.S4 ; J1.S4 16.43,87.42 ; J1.S4 14.6,87.42 ; J1.S4 15.51,88.83 ; J19.3 6.35,15.3 ; J19.3 6.35,13.24 ; J19.3 7.38,14.27 ; J19.3 5.32,14.27 ; J5.5 6.74,61.34 ; J5.5 5.71,62.37 ; J5.5 4.69,61.34 ; J5.5 5.71,60.31 ; J23.2 52.07,43.24 ; J23.2 52.07,41.18 ; J23.2 53.1,42.21 ; J23.2 51.04,42.21 ; J1.S1 8.36,92.63 ; J1.S1 7.45,91.22 ; J1.S1 8.36,89.81 ; J1.S1 9.28,91.22 ; J1.S2 15.51,92.63 ; J1.S2 16.43,91.22 ; J1.S2 15.51,89.81 ; J1.S2 14.6,91.22 ; J22.4 9.92,39.67 ; J22.4 8.89,38.64 ; J22.4 7.86,39.67 ; 5.32,11.73 J19.2 ; J19.2 7.38,11.73 ; J19.2 6.35,12.76 ; J19.2 6.35,10.7
  vias: v1(0.66,72.77) v1(0.74,42.16) v1(0.79,76.58) v1(2.82,75.18) v1(2.95,80.14) v1(2.95,78) v1(3.33,70.61) v1(4.34,90.83) v1(4.34,56.44) v1(4.34,52.45) v1(4.34,49.91) v1(4.34,47.37) v1(4.34,44.83) v1(4.32,40.26) v1(4.34,37.57) v1(4.32,35.18) v1(4.34,32.61) v1(4.34,29.97) v1(4.34,24.89) v1(4.34,22.48) v1(4.34,19.96) v1(4.34,17.48) v1(4.34,14) v1(4.37,88.27) v1(4.37,86.54) v1(4.37,63.2) v1(4.37,61.65) v1(4.37,58.98) v1(4.37,54.51) v1(4.45,27.56) v1(4.39,8.1) v1(4.37,5.44) v1(4.37,3.07) v1(4.57,10.41) v1(4.72,92.18) v1(4.93,64.14) v1(5.05,1.32) v1(5.46,5.46) v1(5.77,88.09) v1(5.92,13) v1(5.99,16.99) v1(6.15,93.27) v1(6.22,23.11) v1(6.35,65.15) v1(6.4,15.77) v1(6.38,10.36) v1(6.76,74.68) v1(6.86,58.04) v1(6.86,2.03) v1(6.91,0.53) v1(7.01,91.31) v1(6.99,87.5) v1(6.99,49.66) v1(7.11,46.99) v1(7.11,6.48) v1(7.24,86.49) v1(7.21,61.72) v1(7.37,18.41) v1(7.57,39.19) v1(7.57,37.03) v1(7.62,31.37) v1(7.59,29.31) v1(7.75,20.29) v1(7.7,11.71) v1(7.77,65.91) v1(7.8,63.91) v1(7.85,26.11) v1(7.82,14.25) v1(8.03,72.77) v1(8.03,4.27) v1(8.26,93.45) v1(8.36,89.33) v1(8.51,48.01) v1(8.51,9.78) v1(8.64,45.09) v1(8.74,60.38) v1(8.81,56.57) v1(8.92,74.93) v1(9.04,68.83) v1(9.04,52.15) v1(8.97,15.85) v1(9.12,9.47) v1(9.42,65.41) v1(9.4,12.57) v1(9.53,88.27) v1(9.73,91.21) v1(9.8,63.63) v1(9.91,4.32) v1(10.03,43.31) v1(10.03,41.61) v1(9.98,22.37) v1(10.06,61.72) v1(10.11,37.62) v1(10.16,52.96) v1(10.19,33.88) v1(10.29,26.16) v1(10.29,20.04) v1(10.29,18.54) v1(10.54,93.45) v1(10.57,56.41) v1(10.74,44.93) v1(10.67,15.49) v1(10.92,27.3) v1(11,91.8) v1(11.02,23.95) v1(11,0.69) v1(11.1,60.15) v1(11.3,86.97) v1(11.3,28.83) v1(11.28,1.96) v1(11.63,86.33) v1(11.68,85.14) v1(11.68,57.66) v1(11.68,34.85) v1(11.84,90.5) v1(11.81,9.27) v1(11.94,26.16) v1(11.96,89.66) v1(11.99,0.53) v1(12.06,33.78) v1(12.12,32.13) v1(12.06,30.1) v1(12.12,18.46) v1(12.06,10.16) v1(12.17,27.36) v1(12.19,10.92) v1(12.32,93.45) v1(12.32,39.75) v1(12.45,41.91) v1(12.78,89.74) v1(12.83,43.05) v1(12.75,23.72) v1(12.9,86.36) v1(12.85,85.27) v1(13.08,46.61) v1(13.06,37.92) v1(13.07,14.91) v1(13.18,48.79) v1(13.21,12.19) v1(13.34,63.63) v1(13.26,44.93) v1(13.26,17.42) v1(13.46,53.34) v1(13.59,50.04) v1(14.02,91.29) v1(14.12,73.91) v1(14.1,54.86) v1(14.17,82.27) v1(14.25,41.81) v1(14.33,93.4) v1(14.35,89.79) v1(14.53,0.53) v1(14.73,83.41) v1(14.68,31.17) v1(14.73,27.58) v1(14.68,14.38) v1(14.76,81.69) v1(14.76,62.08) v1(14.94,89.05) v1(14.86,57.66) v1(14.88,43.31) v1(14.99,40.39) v1(15.04,10.97) v1(15.24,16.99) v1(15.47,82.65) v1(15.46,36.83) v1(15.54,13.23) v1(15.57,15.64) v1(15.75,51.82) v1(15.77,80.62) v1(16.13,19.35) v1(16.15,17.73) v1(16.31,53.14) v1(16.28,29.97) v1(16.28,25.32) v1(16.36,93.42) v1(16.38,81.76) v1(16.48,89.56) v1(16.46,79.93) v1(16.54,36.09) v1(16.51,10.46) v1(16.59,86.23) v1(16.64,49.78) v1(16.74,87.02) v1(16.69,14.47) v1(16.76,92.08) v1(16.79,8.51) v1(16.92,63.22) v1(16.89,47.24) v1(16.87,27.69) v1(17.07,79.38) v1(17.14,55.12) v1(17.14,5.21) v1(17.07,0.53) v1(17.17,80.92) v1(17.17,43.31) v1(17.35,44.98) v1(17.27,23.77) v1(17.5,22.96) v1(17.48,19.73) v1(17.63,78.82) v1(17.65,17.98) v1(17.81,80.31) v1(17.78,21.54) v1(18.03,57.91) v1(17.98,12.62) v1(18.11,86.21) v1(18.29,93.45) v1(18.34,79.76) v1(18.34,41.48) v1(18.39,22.83) v1(18.47,78.56) v1(18.47,10.34) v1(18.67,83.85) v1(18.67,53.21) v1(18.67,51.56) v1(18.8,87.38) v1(18.92,57.33) v1(19.08,89.99) v1(19.33,79.76) v1(19.25,36.53) v1(19.28,19.12) v1(19.38,78.56) v1(19.43,24.89) v1(19.48,34.01) v1(19.63,21.95) v1(19.61,0.53) v1(19.66,82.91) v1(19.81,47.5) v1(19.81,43.31) v1(19.86,90.02) v1(19.94,41.4) v1(19.86,27.71) v1(20.14,4.65) v1(20.29,78.54) v1(20.35,38.94) v1(20.45,10.31) v1(20.52,46.66) v1(20.73,91.26) v1(20.65,88.01) v1(20.68,81.76) v1(20.7,32.18) v1(20.83,55.63) v1(20.83,33.48) v1(20.78,18.82) v1(20.9,92.3) v1(20.9,22.71) v1(20.98,37.69) v1(21.01,28.83) v1(20.95,24.84) v1(21.18,36.14) v1(21.34,93.45) v1(21.34,16.99) v1(21.34,9.02) v1(21.49,57.28) v1(21.46,45.21) v1(21.54,22.3) v1(21.55,50.16) v1(21.56,21.49) v1(21.64,20.73) v1(21.72,80.85) v1(21.69,71.04) v1(21.72,69.04) v1(21.74,67.87) v1(21.69,25.52) v1(21.74,20.04) v1(21.79,90.73) v1(21.84,41.27) v1(21.87,19.33) v1(22.05,18.64) v1(22.12,33.4) v1(22.12,32.23) v1(22.1,26.69) v1(22.15,0.53) v1(22.33,72.82) v1(22.25,17.93) v1(22.25,15.16) v1(22.38,37.64) v1(22.4,36.17) v1(22.35,29.64) v1(22.48,56.9) v1(22.48,27.89) v1(22.48,24.97) v1(22.48,17.3) v1(22.73,43.81) v1(22.73,16.69) v1(22.91,70.71) v1(22.86,22.58) v1(22.86,21.74) v1(22.91,21.08) v1(22.99,46.56) v1(22.99,20.4) v1(23.01,16.08) v1(23.11,19.76) v1(23.16,28.9) v1(23.27,19.1) v1(23.34,15.47) v1(23.39,68) v1(23.39,49.45) v1(23.5,52.58) v1(23.5,24.86) v1(23.47,18.44) v1(23.47,13.18) v1(23.62,56.77) v1(23.6,36.14) v1(23.6,33.38) v1(23.65,32.38) v1(23.75,44.83) v1(23.7,37.62) v1(23.7,26.72) v1(23.72,22.45) v1(23.67,17.83) v1(23.72,14.83) v1(23.8,47.68) v1(23.88,93.45) v1(23.85,27.89) v1(23.93,17.2) v1(24,69.98) v1(24.13,58.29) v1(24.13,14.25) v1(24.16,25.52) v1(24.23,16.56) v1(24.59,15.9) v1(24.56,13.67) v1(24.71,57.43) v1(24.71,37.62) v1(24.74,34.9) v1(24.71,28.95) v1(24.69,0.53) v1(24.84,36.14) v1(24.89,86.74) v1(24.92,69.65) v1(24.87,68.2) v1(24.94,33.4) v1(24.89,24.86) v1(24.94,15.34) v1(24.89,4.95) v1(24.97,32.26) v1(24.99,21.98) v1(25.02,13.11) v1(25.15,11.38) v1(25.2,27.89) v1(25.2,26.72) v1(25.25,25.55) v1(25.27,47.5) v1(25.35,38.07) v1(25.3,20.11) v1(25.35,14.78) v1(25.4,18.95) v1(25.43,12.68) v1(25.63,65.07) v1(25.72,14.28) v1(25.86,12.2) v1(25.91,2.64) v1(26.04,67.23) v1(25.98,58.75) v1(25.96,21.99) v1(26.11,13.85) v1(26.16,44.96) v1(26.16,9.73) v1(26.29,38.99) v1(26.29,34.92) v1(26.29,28.7) v1(26.29,27.87) v1(26.29,11.76) v1(26.42,93.45) v1(26.39,62.94) v1(26.42,26.67) v1(26.47,16.36) v1(26.64,22.88) v1(26.62,13.31) v1(26.72,66.45) v1(26.72,10.34) v1(26.85,17.55) v1(26.82,11.21) v1(27.03,63.93) v1(27.15,12.75) v1(27.2,10.77) v1(27.23,0.53) v1(27.34,68.17) v1(27.38,88.34) v1(27.38,73.66) v1(27.38,70.51) v1(27.38,20.34) v1(27.43,14.4) v1(27.43,5.08) v1(27.51,90.47) v1(27.46,87.07) v1(27.69,21.89) v1(27.66,18.87) v1(27.71,10.39) v1(27.74,9.04) v1(27.76,13.16) v1(27.94,44.96) v1(27.94,37.69) v1(27.94,34.82) v1(27.94,32) v1(27.99,36.04) v1(27.97,33.71) v1(27.99,28.9) v1(28.09,89.36) v1(28.07,86.74) v1(28.07,48.01) v1(28.07,41.66) v1(28.14,27.9) v1(28.07,25.53) v1(28.14,9.96) v1(28.17,26.69) v1(28.24,11.76) v1(28.24,8.51) v1(28.32,13.74) v1(28.45,85.85) v1(28.37,43.92) v1(28.45,24.74) v1(28.68,65.18) v1(28.7,38.99) v1(28.65,12.19) v1(28.68,11.25) v1(28.83,37.97) v1(28.83,14.2) v1(28.85,8) v1(28.96,93.45) v1(29.03,69.04) v1(28.96,34.92) v1(28.96,32) v1(29.08,74.68) v1(29.08,68.22) v1(29.08,12.6) v1(29.08,10.83) v1(29.13,2.67) v1(29.21,73.53) v1(29.21,69.85) v1(29.21,55.75) v1(29.18,17.47) v1(29.31,6.71) v1(29.44,8.67) v1(29.46,84.99) v1(29.54,15.9) v1(29.51,14.27) v1(29.57,62.94) v1(29.64,12.95) v1(29.67,90.75) v1(29.74,83.46) v1(29.74,68) v1(29.77,0.53) v1(29.87,6.1) v1(29.87,4.83) v1(30,11.35) v1(30.1,46.86) v1(30.07,7.98) v1(30.25,17.47) v1(30.3,12.93) v1(30.28,9.58) v1(30.43,10.92) v1(30.53,77.62) v1(30.53,75.08) v1(30.51,73.41) v1(30.53,71.75) v1(30.51,69.95) v1(30.53,68.71) v1(30.51,66.78) v1(30.45,64.74) v1(30.73,7.27) v1(30.86,28.96) v1(30.86,27.94) v1(30.86,26.67) v1(30.86,10.46) v1(31.11,78.26) v1(31.11,62.99) v1(31.11,58.67) v1(31.14,16.84) v1(31.09,5.54) v1(31.11,0.56) v1(31.24,14.25) v1(31.22,1.52) v1(31.27,12.93) v1(31.27,9.87) v1(31.29,6.73) v1(31.5,93.45) v1(31.47,88.32) v1(31.5,45.09) v1(31.47,11.68) v1(31.62,84.35) v1(31.57,80.49) v1(31.62,4.88) v1(31.62,4.04) v1(31.62,3.28) v1(31.62,2.34) v1(31.7,8.28) v1(31.75,39.09) v1(31.78,37.94) v1(31.75,24.81) v1(31.8,6.3) v1(31.93,34.97) v1(31.93,31.87) v1(31.88,17.47) v1(32,28.93) v1(31.98,27.89) v1(32,26.74) v1(32,25.55) v1(31.95,14.25) v1(31.98,12.93) v1(32.05,79.63) v1(32.16,78.18) v1(32.33,7.62) v1(32.31,5.71) v1(32.36,16.1) v1(32.59,14.25) v1(32.61,12.9) v1(32.66,8.61) v1(33.05,73.18) v1(33.02,71.88) v1(32.99,70.43) v1(32.99,68.78) v1(32.99,66.95) v1(32.99,65.35) v1(32.97,17.47) v1(33.17,77.47) v1(33.17,11.2) v1(33.4,14.53) v1(33.5,28.9) v1(33.45,24.86) v1(33.48,12.67) v1(33.5,6.3) v1(33.68,34.97) v1(33.66,16.33) v1(33.71,9.7) v1(33.81,37.64) v1(33.83,5.69) v1(33.93,36.2) v1(33.93,12.22) v1(34.04,93.45) v1(33.99,31.85) v1(33.96,27.89) v1(34.04,26.74) v1(34.04,17.47) v1(33.96,14.88) v1(34.14,11.43) v1(34.16,92.08) v1(34.32,25.55) v1(34.42,22.53) v1(34.47,15.7) v1(34.59,28.93) v1(34.67,39.06) v1(34.67,33.86) v1(34.8,57.28) v1(34.8,5.69) v1(35,11.43) v1(35.1,77.34) v1(35.1,74.55) v1(35.1,70.99) v1(35.1,67.44) v1(35.1,64.26) v1(35.1,24.71) v1(35.28,15.72) v1(35.61,39.04) v1(35.59,37.62) v1(35.56,36.2) v1(35.61,34.36) v1(35.64,31.95) v1(35.64,28.8) v1(35.69,19.76) v1(35.69,16.33) v1(35.69,5.69) v1(35.81,25.78) v1(35.79,11.46) v1(36.04,27.89) v1(35.97,15.7) v1(36.02,9.57) v1(36.09,7.79) v1(36.3,45.31) v1(36.53,57.58) v1(36.52,38.53) v1(36.53,29.33) v1(36.58,93.45) v1(36.58,35.28) v1(36.68,33.83) v1(36.7,14.81) v1(36.7,11.76) v1(36.93,13.67) v1(37.03,5.69) v1(37.19,39.21) v1(37.44,22.78) v1(37.52,7.21) v1(37.59,47.62) v1(37.67,24.71) v1(37.72,16.33) v1(37.72,13.15) v1(37.95,20.62) v1(38.1,4.42) v1(38.13,3.48) v1(38.13,2.36) v1(38.23,5.36) v1(38.28,18.44) v1(38.48,23.19) v1(38.73,14.81) v1(38.79,57.4) v1(38.79,39.01) v1(38.79,35.3) v1(38.86,37.72) v1(38.89,11.4) v1(38.89,1.5) v1(38.89,0.53) v1(38.99,44.37) v1(38.96,33.8) v1(39.01,26.95) v1(39.01,24.71) v1(39.12,93.45) v1(39.24,4.44) v1(39.32,2.67) v1(39.5,30.35) v1(39.65,6.6) v1(39.78,8.63) v1(39.88,28.27) v1(40.21,48.9) v1(40.23,16.84) v1(40.34,91.29) v1(40.26,63.63) v1(40.26,62.1) v1(40.44,88.57) v1(40.36,22.15) v1(40.64,23.62) v1(40.56,5.36) v1(40.72,31.7) v1(40.69,1.78) v1(40.89,29.72) v1(40.94,27.03) v1(41.02,57.53) v1(41.02,35.05) v1(41.15,39.88) v1(41.15,37.72) v1(41.07,21.21) v1(41.25,79.02) v1(41.33,19.1) v1(41.4,15.11) v1(41.66,93.45) v1(41.76,89.81) v1(41.78,12.45) v1(41.78,4.47) v1(41.86,21) v1(42,45.44) v1(41.99,8.43) v1(42.14,29.57) v1(42.09,0.56) v1(42.18,26.9) v1(42.19,6.6) v1(42.29,25.3) v1(42.34,23.8) v1(42.42,16.64) v1(42.55,20.42) v1(42.67,70.33) v1(43.31,61.47) v1(43.33,2.01) v1(43.43,39.75) v1(43.43,18.67) v1(43.56,45.72) v1(43.81,5.41) v1(43.94,10.54) v1(44.02,36.04) v1(44.04,17.88) v1(44.07,38.48) v1(44.15,22.31) v1(44.12,21.44) v1(44.09,20.55) v1(44.07,16.76) v1(44.07,13.46) v1(44.2,93.45) v1(44.2,69.7) v1(44.58,72.11) v1(45.03,45.62) v1(45.03,0.56) v1(45.21,91.41) v1(45.17,7.11) v1(45.72,9.78) v1(45.85,72.24) v1(45.8,45.64) v1(45.97,79.04) v1(45.97,17.27) v1(46.1,87) v1(46.1,41.4) v1(46.1,35.81) v1(46.1,34.92) v1(46.1,32.38) v1(46.1,31.37) v1(46.1,27.81) v1(46.1,26.8) v1(46.1,22.61) v1(46.1,20.57) v1(46.1,19.81) v1(46.1,14.22) v1(46.23,47.88) v1(46.23,34.29) v1(46.23,15.88) v1(46.33,24.97) v1(46.74,93.45) v1(46.74,62.48) v1(46.86,69.57) v1(47.02,54.84) v1(47.12,71.22) v1(47.4,0.58) v1(47.62,3.07) v1(48.26,4.62) v1(48.84,46.18) v1(48.92,93.42) v1(49.43,87.68) v1(49.4,12.19) v1(49.78,73) v1(49.89,90.22) v1(49.91,17.27) v1(50.04,36.12) v1(50.16,46.99) v1(50.55,14.22) v1(50.67,41.53) v1(50.67,18.67) v1(50.8,72.36) v1(50.77,40.51) v1(50.8,31.88) v1(50.77,27.61) v1(50.8,22.99) v1(50.88,48.44) v1(50.9,39.12) v1(50.93,20.45) v1(50.93,12.57) v1(50.93,11.05) v1(50.95,43.1) v1(51.05,0.51) v1(51.18,3.05) v1(51.31,44.53) v1(51.31,35.94) v1(51.36,15.93) v1(51.69,45.59) v1(51.69,6.48) v1(51.87,80.31) v1(52.15,93.34) v1(52.25,87.71) v1(52.7,10.41) v1(52.93,1.02) v1(53.21,92.81) v1(53.47,14.35) v1(53.85,45.49) v1(53.9,31.52) v1(54.03,62.23) v1(53.98,57.91) v1(53.98,33.78) v1(54.04,28.8) v1(53.98,20.95) v1(54.08,49.68) v1(54.08,47.09) v1(54.08,41.96) v1(54.08,39.07) v1(54.05,36.6) v1(54.08,27.41) v1(54.05,18.16) v1(54.05,15.77) v1(54.05,12.93) v1(54.05,10.39) v1(54.05,7.85) v1(54.05,5.31) v1(54.05,2.77) v1(57.58,88.14) v1(57.58,85.09) v1(57.58,82.55) v1(57.58,80.01) v1(57.58,77.47) v1(57.58,74.93) v1(57.58,72.39) v1(57.58,69.85) v1(57.58,67.31) v1(57.58,64.77) v1(57.89,91.69)
VBAT_CC: length 45.7
  TOP w0.406: R112.2 31.72,48.89 31.72,49.69 v1(31.5,49.91) ; 33.27,49.99 J12.1 ; J12.1 34.34,51.05 ; J12.1 33.27,52.12 ; J12.1 32.21,51.05
  TOP w0.762: 29.82,22.35 29.84,22.37 v1(30.56,22.37) v1(31.19,22.37) 33.12,22.37 33.15,22.4 ; 29.82,22.35 29.08,22.35 28.55,22.89 U1.36 ; 29.82,22.35 U1.37 ; U1.40 33.63,22.88 33.15,22.4 ; 33.15,22.4 v1(32.44,22.4) v1(31.85,22.4)
  MID2(L3) w1.016: J12.1 33.27,48.51 29.84,45.09 29.84,23.77 30.91,22.71
  vias: v1(31.5,50.55)
VBUS_USB1: length 4.1
  TOP w0.254: U5.42 v1(25.04,70.67) ; U5.3 23.72,74.17 23.8,74.09 v1(23.8,74.05) ; U5.4 23.22,74.05 v1(23.22,74.04)
  TOP w0.305: R338.2 v1(27.89,76.07)
  vias: v1(24.66,85.42) v1(24.66,84.84) v1(25.27,85.42) v1(25.3,84.84)
VCC_BRD: length 141
  TOP w0.305: R173.2 v1(47.98,63.88) ; R98.2 v1(54.61,68.96) ; R168.1 10.13,7.77 v1(10.16,7.75) ; v1(47.12,82.68) R226.1 ; R99.2 v1(48.64,73.79) ; R101.2 v1(55.78,75.84) ; R172.2 v1(50.06,69.19) ; R86.2 v1(53.57,78.64)
  TOP w0.406: J12.2 33.27,54.66 ; J12.2 32.21,53.59 ; J12.2 34.34,53.59 ; L11.1 38.01,80.14 U8.1 ; D1.1 v1(38.86,86.58) ; v1(35.81,86.87) 35.69,87 R64.1 ; v1(18.44,60.48) C70.1 U11.1 ; D5.1 v1(15.29,2.66) ; U12.5 v1(23.47,62.23) ; D6.1 v1(20.12,2.61) ; R9.1 v1(52.32,58.42) ; U12.1 C68.1 v1(18.44,62.1) 18.34,62 R347.2 ; D7.1 v1(25.1,2.61)
  MID2(L3) w0.406: 33.27,52.58 J12.2 ; J12.2 32.26,53.59 ; J12.2 33.27,54.61 ; J12.2 34.29,53.59 ; 42.21,51.05 J13.1 43.23,52.07
  MID2(L3) w0.762: 20.07,2.66 25.04,2.66 v1(25.1,2.61) ; 20.07,2.66 v1(20.12,2.61) ; 20.07,2.66 v1(15.29,2.66) 10.21,7.75 v1(10.16,7.75) 10.11,7.8 5.97,7.8 1.93,11.84 1.93,39.78 4.37,42.21 J22.1
  BOTTOM w0.406: v1(18.44,60.48) v1(18.44,62.1)
  BOTTOM w0.508: v1(34.8,62.23) v1(23.47,62.23) 21.72,60.48 v1(18.44,60.48)
  BOTTOM w0.762: J22.1 8.21,44.07 20.27,44.07 v1(20.52,43.81) 21.19,43.81 23.22,45.85 27.05,45.85 30.54,49.34 30.54,53.66 v1(31.37,54.48)
  vias: v1(41.83,82.98) v1(41.83,82.35) v1(47.14,7.72) v1(47.78,7.72)
VCC_DCDC_3V3: length 2.5
  TOP w0.406: 33.85,83.34 U8.4 ; 33.85,83.34 32.77,83.34 R110.2 ; 33.85,83.34 C63.1
VCC_LDO_3V3: length 44.9
  TOP w0.254: C57.1 22.22,64.93 U5.31 ; v1(11.94,76.71) C77.1 11.43,76.68 U7.14 ; v1(15.34,74.07) C56.1 16.05,74.07 16.95,73.17 U5.14
  TOP w0.305: v1(21.56,88.01) 21.59,87.99 C31.1 R56.2 ; R342.1 29.31,78.94 v1(29.26,78.89) ; U2.8 25.44,81.13 C58.1 v1(23.09,81.13) ; U12.6 23.66,63.18 C69.1 v1(23.85,64.03) ; v1(31.85,78.94) R32.1 ; U11.6 24.09,59.75 C72.1 24.1,59.77 v1(24.51,60.17) ; R302.1 v1(26.11,78.89) ; C57.1 v1(21.54,64.92) R34.1
  TOP w0.356: U7.4 v1(7.24,73.41) ; U9.1 v1(6.73,69.64) ; v1(9.93,82.78) 9.93,82.8 10.44,83.31 C75.1 11.43,83.24 U4.14
  TOP w0.406: R314.1 14.61,70.61 v1(14.48,70.48) ; U9.14 13.02,69.64 C76.1 13.46,69.32 v1(13.46,69.22) ; R318.1 v1(3.28,79.6) ; R315.1 v1(14.48,79.38) ; v1(4.22,82.93) D2.1
  TOP w0.508: R30.1 v1(18.03,77.09)
  TOP w1.143: J13.2 43.23,55.16 43.18,55.21
  BOTTOM w0.305: v1(31.85,78.94) 31.8,78.89 v1(29.26,78.89) v1(26.11,78.89)
  BOTTOM w0.406: v1(3.28,79.6) 4.22,80.55 v1(4.22,82.93) 4.48,82.68 v1(7.37,82.68)
  vias: v1(18.26,74.52) v1(19.08,73.76) v1(22.07,76.76) v1(22.17,88.01) v1(26.69,60.7) v1(26.67,60.07) v1(27.27,60.72) v1(27.25,60.07)
VCC_MCU_5V: length 100.1
  TOP w0.508: v1(11.4,84.05) R109.2
  TOP w0.762: J22.2 7.37,43.74 3.6,43.74 0.76,40.89 0.76,11.81 3.38,9.19 J19.1
  MID2(L3) w0.508: J22.2 7.87,43.23 7.87,62.74 4.7,65.91 4.7,81.03 7.75,84.07 11.38,84.07 v1(11.4,84.05)
VDD_FLASH: length 63.5
  TOP w0.406: R112.1 v1(30.84,47.98) ; R110.1 v1(32.77,81.79) ; U1.39 32.36,24.53 32.74,24.91 v1(32.77,24.91)
  MID2(L3) w0.406: v1(32.77,81.79) 32.77,80.64 34.54,78.87 34.54,63.88 29.97,59.31 29.97,48.84 v1(30.84,47.98) ; v1(32.77,45.59) v1(32.77,24.91)
  BOTTOM w0.406: v1(30.84,47.98) 32.77,46.05 v1(32.77,45.59)
BRD_JTAG_TCK: length 30.5
  TOP w0.127: R320.2 v1(13.74,80.01)
  BOTTOM w0.127: v1(13.74,80.01) 12.7,78.97 12.7,68.99 15.49,66.19 15.49,56.87 J8.1
BRD_JTAG_TDI: length 26.5
  TOP w0.127: v1(13.72,77.32) R321.2
  BOTTOM w0.127: J10.1 15.75,55.63 15.75,66.3 12.95,69.09 12.95,76.58 13.69,77.32 v1(13.72,77.32)
BRD_JTAG_TDO: length 22.6
  TOP w0.127: R324.2 13.21,72.77 v1(13.46,72.52)
  BOTTOM w0.127: v1(13.46,72.52) 16.36,69.62 16.36,58.06 J11.1
BRD_JTAG_TMS: length 27.1
  TOP w0.127: R323.2 2.16,73.18 2.16,65.91 3.17,64.9 5.34,64.9 14.61,55.63 J9.1
CC_GPIO_00: length 44.2
  TOP w0.127: v1(44.2,33.19) 44.68,33.68 R344.1 ; U1.44 36.98,25.6 36.32,26.26 v1(36.32,27.02) ; v1(15.34,19.35) R335.2
  BOTTOM w0.127: v1(44.2,33.19) 43.35,33.19 37.18,27.02 v1(36.32,27.02) 36.14,27.2 21.47,27.2 20.94,26.67 15.67,26.67 14.64,25.64 14.64,22.54 15.34,21.84 v1(15.34,19.35)
CC_GPIO_01: length 32.5
  TOP w0.127: J7.2 29.36,52.55 29.36,46.58 31.5,44.45 v1(36.06,44.45) ; v1(36.37,28.75) 36.98,28.14 U1.46
  MID2(L3) w0.127: v1(36.06,44.45) 36.06,29.07 v1(36.37,28.75)
CC_GPIO_02: length 36.1
  TOP w0.127: J6.2 26.42,52.32 28.7,52.32 29.11,51.92 29.11,46.46 31.55,44.02 38.05,44.02 v1(38.1,44.07) ; U1.47 v1(38.51,29.41)
  MID2(L3) w0.127: v1(38.1,44.07) 38.1,34.67 38.09,34.66 38.09,34.32 38.1,34.31 38.1,29.82 v1(38.51,29.41)
CC_GPIO_03: length 47.2
  TOP w0.127: U1.48 36.83,30.68 v1(36.58,30.93) ; R10.1 1.57,40.16 2.31,40.89 13.77,40.89 14.73,39.93 15.04,39.62 15.04,32.31 v1(14.68,31.95) 14.68,31.95 14.15,31.42 R346.2
  BOTTOM w0.127: v1(14.68,31.95) 15.7,30.93 v1(36.58,30.93)
CC_GPIO_04: length 41.8
  TOP w0.127: v1(2.87,30.56) 2.29,30.56 1.57,29.84 R22.1 ; U1.49 v1(38.99,31.95) ; v1(14.43,29.49) 14.4,29.51 R340.2
  BOTTOM w0.127: v1(38.99,31.95) 37.5,30.46 15.58,30.46 14.61,29.49 v1(14.43,29.49) 13.23,30.68 3,30.68 v1(2.87,30.56)
CC_GPIO_05: length 63
  TOP w0.127: v1(14.35,34.29) 14.3,34.34 R312.2 ; U1.50 v1(36.71,33.22) ; J5.2 6.32,53.72 v1(8.99,51.05) ; v1(40.08,24.38) R301.1
  MID2(L3) w0.127: v1(8.99,51.05) 9.53,50.52 9.53,44.83 11.18,43.18 11.18,37.77 14.35,34.59 v1(14.35,34.29) ; v1(40.08,24.38) 40.08,27.07 37.85,29.31 37.85,32.08 v1(36.71,33.22)
  BOTTOM w0.127: v1(14.35,34.29) 14.35,34.19 14.39,34.15 14.39,34.08 15.57,32.89 36.37,32.89 36.7,33.22 v1(36.71,33.22)
CC_GPIO_06: length 50.6
  TOP w0.127: v1(2.92,32.92) 2.06,32.92 1.57,32.44 R231.1 ; U1.51 v1(38.51,34.49) 41.46,34.49 v1(42.16,33.78) ; R307.1 v1(42.65,30.93)
  MID2(L3) w0.127: v1(42.16,33.78) 42.62,33.32 42.62,30.96 v1(42.65,30.93)
  BOTTOM w0.127: v1(38.51,34.49) 38.51,32.8 37.13,31.41 16.01,31.41 14.07,33.35 3.35,33.35 v1(2.92,32.92)
